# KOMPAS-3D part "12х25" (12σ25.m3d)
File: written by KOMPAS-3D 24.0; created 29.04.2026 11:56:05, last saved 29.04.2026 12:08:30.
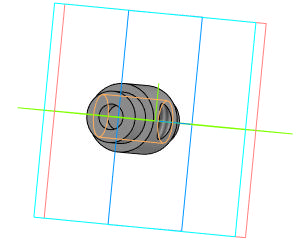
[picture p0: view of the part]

Document properties: Автор: USG_411; Полное имя файла: C:\Users\USG_411\Desktop\ИА-2904_411-12\12х25.m3d

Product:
- Part/product: 12х25
    Масса: 0.028419

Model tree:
1. Эскиз:1
2. Элемент выдавливания:1
     Расстояние 2 = 30
3. Смещенная плоскость:1
     Расстояние = 7
4. Эскиз:2
5. Элемент выдавливания:2
     Расстояние 2 = 16
6. Эскиз:3  (with: Ребро.Элемент выдавливания:2)
7. Элемент выдавливания:3
     Расстояние 1 = 8; Расстояние 2 = 8
8. Условное изображение резьбы:1  (with: Грань.Элемент выдавливания:3, Ребро.Элемент выдавливания:3)  (labels: M10; cil0_24705-2004 coarse)
     Длина резьбы = 16; Шаг резьбы = 1.5; Номинальный диаметр резьбы = 10
9. Подгонка:1  (with: Грань.Элемент выдавливания:3)
10. Эскиз:4  (with: Грань.Элемент выдавливания:1)
11. Элемент выдавливания:4
     Расстояние 2 = 6
12. Эскиз:5  (with: Грань.Элемент выдавливания:1)
13. Элемент выдавливания:6
     Расстояние 2 = 6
